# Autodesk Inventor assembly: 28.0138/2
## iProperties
Created: 2007-06
Part Number: 28.0138/2
Document SubType Name: Assembly
Designer: Andy Moles
Description: SLIDE LR 6 WITH COVERS AND TENSIONERS
Author: Andy Moles
